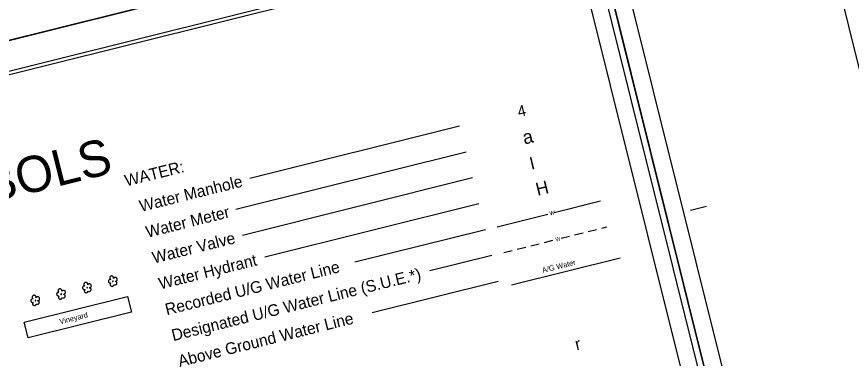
# Model space of a CAD drawing. Extents: x 1030323 to 1034123, y 654802 to 657751.
# Drawn here: x 1031795 to 1032422, y 655929 to 656186 of the extents above; entities that cross this region are included whole.
import ezdxf

# ---------------------------------------------------------------- set-up
doc = ezdxf.new("R2010")
doc.units = 0
for name, color, linetype in [('Sheet Cutting Line CELL', 7, 'Continuous'), ('Sheet Plot Border Inside CELL', 7, 'Continuous'), ('Sheet Plot Border Outside CELL', 7, 'Continuous'), ('Sheet Summary CELL', 7, 'Continuous'), ('Sheet Symbology CELL', 7, 'Continuous')]:
    doc.layers.add(name, color=color, linetype=linetype)

msp = doc.modelspace()

# ---------------------------------------------------------------- linework, layer by layer
at = {"layer": 'Sheet Cutting Line CELL'}
for p, q in [((1030589.1, 655869.05), (1032223.08, 656276.44)), ((1032223.08, 656276.44), (1030589.1, 655869.05)), ((1032223.08, 656276.44), (1032489.19, 655209.12))]:
    msp.add_line(p, q, dxfattribs=at)
at = {"layer": 'Sheet Plot Border Inside CELL'}
for points in [[(1033858.12, 656660.97), (1032241.12, 656257.81), (1032496.37, 655234.05), (1034113.37, 655637.21)], [(1030862.39, 654826.65), (1032479.39, 655229.81), (1032224.14, 656253.57), (1030607.14, 655850.41)]]:
    msp.add_lwpolyline(points, close=True, dxfattribs=at)
at = {"layer": 'Sheet Plot Border Outside CELL'}
for points in [[(1031956.96, 657343.76), (1030322.99, 656936.36), (1030589.1, 655869.05), (1032223.08, 656276.44)], [(1033857.05, 656683.84), (1032223.08, 656276.44), (1032489.19, 655209.12), (1034123.17, 655616.52)], [(1030855.21, 654801.72), (1032489.19, 655209.12), (1032223.08, 656276.44), (1030589.1, 655869.05)]]:
    msp.add_lwpolyline(points, close=True, dxfattribs=at)
at = {"layer": 'Sheet Summary CELL'}
msp.add_line((1032300.9, 656040.77), (1032313.03, 656043.8), dxfattribs=at)
msp.add_lwpolyline([(1033846.61, 656655.47), (1032391.16, 656292.59), (1032645.18, 655273.78), (1034100.62, 655636.66)], close=True, dxfattribs=at)
at = {"layer": 'Sheet Symbology CELL'}
for p, q in [((1032127.56, 656103.71), (1031970, 656064.42)), ((1032132.4, 656084.3), (1031959.65, 656041.23)), ((1032137.24, 656064.9), (1031964.49, 656021.82)), ((1032142.08, 656045.49), (1031981.22, 656005.38)), ((1032198.65, 656038.98), (1032233.29, 656047.62)), ((1032155.66, 656028.26), (1032193.8, 656037.77)), ((1032146.92, 656026.08), (1032048.81, 656001.62)), ((1032224.12, 656024.72), (1032230.42, 656026.29)), ((1032234.31, 656027.26), (1032238.13, 656028.21)), ((1032191.22, 656016.52), (1032197.53, 656018.09)), ((1032203.74, 656019.64), (1032210.05, 656021.21)), ((1032213.93, 656022.18), (1032220.24, 656023.75)), ((1032170.85, 656011.44), (1032177.15, 656013.01)), ((1032181.04, 656013.98), (1032187.34, 656015.55)), ((1032151.76, 656006.68), (1032105.17, 655995.06)), ((1032160.66, 656008.9), (1032166.97, 656010.47)), ((1032166.55, 655984.6), (1032248.07, 656004.93)), ((1032156.6, 655987.27), (1032061.79, 655963.63))]:
    msp.add_line(p, q, dxfattribs=at)
msp.add_lwpolyline([(1032212.63, 656248.07), (1030757.19, 655885.19), (1031010.96, 654867.37), (1032466.4, 655230.25)], close=True, dxfattribs=at)
for points in [[(1031848.31, 655984.64), (1031848.38, 655984.97), (1031848.36, 655985.28), (1031848.23, 655985.55), (1031848.11, 655985.83), (1031847.91, 655986.04), (1031847.7, 655986.25), (1031847.41, 655986.38), (1031847.13, 655986.46), (1031846.77, 655986.48), (1031846.53, 655986.42), (1031846.25, 655986.3), (1031845.98, 655986.13), (1031845.77, 655985.92), (1031845.58, 655985.66), (1031845.51, 655985.34), (1031845.47, 655985.07), (1031845.49, 655984.77), (1031845.57, 655984.48), (1031845.69, 655984.2), (1031845.89, 655983.99), (1031846.16, 655983.75), (1031845.88, 655983.83), (1031845.58, 655983.81), (1031845.29, 655983.74), (1031845.07, 655983.58), (1031844.85, 655983.42), (1031844.66, 655983.17), (1031844.51, 655982.92), (1031844.42, 655982.65), (1031844.44, 655982.39), (1031844.47, 655982.04), (1031844.58, 655981.81), (1031844.74, 655981.59), (1031844.99, 655981.4), (1031845.19, 655981.24), (1031845.47, 655981.15), (1031845.79, 655981.08), (1031846.05, 655981.09), (1031846.34, 655981.17), (1031846.12, 655981.01), (1031845.93, 655980.75), (1031845.83, 655980.52), (1031845.81, 655980.21), (1031845.78, 655979.89), (1031845.84, 655979.65), (1031845.96, 655979.37), (1031846.17, 655979.16), (1031846.38, 655978.96), (1031846.62, 655978.81), (1031846.9, 655978.73), (1031847.16, 655978.69), (1031847.45, 655978.76), (1031847.75, 655978.84), (1031847.98, 655978.95), (1031848.17, 655979.2), (1031848.38, 655979.41), (1031848.51, 655979.9)], [(1031867.71, 655989.48), (1031867.79, 655989.81), (1031867.76, 655990.11), (1031867.64, 655990.39), (1031867.52, 655990.67), (1031867.31, 655990.88), (1031867.11, 655991.08), (1031866.82, 655991.22), (1031866.54, 655991.3), (1031866.17, 655991.32), (1031865.93, 655991.25), (1031865.65, 655991.13), (1031865.39, 655990.96), (1031865.18, 655990.76), (1031864.98, 655990.5), (1031864.91, 655990.18), (1031864.88, 655989.91), (1031864.9, 655989.61), (1031864.97, 655989.31), (1031865.09, 655989.04), (1031865.3, 655988.83), (1031865.57, 655988.59), (1031865.29, 655988.67), (1031864.98, 655988.65), (1031864.69, 655988.58), (1031864.47, 655988.42), (1031864.26, 655988.26), (1031864.06, 655988.01), (1031863.92, 655987.76), (1031863.83, 655987.48), (1031863.84, 655987.23), (1031863.88, 655986.88), (1031863.99, 655986.65), (1031864.15, 655986.43), (1031864.4, 655986.24), (1031864.59, 655986.08), (1031864.87, 655985.99), (1031865.2, 655985.92), (1031865.45, 655985.93), (1031865.75, 655986), (1031865.53, 655985.85), (1031865.33, 655985.59), (1031865.24, 655985.36), (1031865.21, 655985.05), (1031865.19, 655984.73), (1031865.25, 655984.49), (1031865.37, 655984.21), (1031865.57, 655984), (1031865.78, 655983.8), (1031866.02, 655983.65), (1031866.3, 655983.57), (1031866.57, 655983.53), (1031866.86, 655983.6), (1031867.15, 655983.67), (1031867.38, 655983.78), (1031867.58, 655984.04), (1031867.78, 655984.24), (1031867.92, 655984.74)], [(1031867.31, 655987.58), (1031867.17, 655987.54), (1031867.08, 655987.47), (1031867, 655987.4), (1031867.03, 655987.25), (1031867.06, 655987.16), (1031867.18, 655987.08), (1031867.32, 655987.12), (1031867.42, 655987.14), (1031867.49, 655987.26), (1031867.51, 655987.42), (1031867.43, 655987.51), (1031867.31, 655987.58)], [(1031867.92, 655984.74), (1031868.58, 655984.55), (1031868.9, 655984.52), (1031869.2, 655984.55), (1031869.48, 655984.67), (1031869.7, 655984.83), (1031869.9, 655985.03), (1031870.1, 655985.29), (1031870.18, 655985.56), (1031870.22, 655985.83), (1031870.25, 655986.15), (1031870.12, 655986.43), (1031870, 655986.7), (1031869.74, 655986.95), (1031869.54, 655987.1), (1031869.26, 655987.19), (1031868.94, 655987.26), (1031869.24, 655987.29), (1031869.58, 655987.37), (1031869.8, 655987.53), (1031870.05, 655987.75), (1031870.26, 655987.95), (1031870.39, 655988.24), (1031870.46, 655988.57), (1031870.44, 655988.87), (1031870.42, 655989.18), (1031870.3, 655989.46), (1031870.13, 655989.72), (1031869.87, 655989.92), (1031869.57, 655990.1), (1031869.29, 655990.19), (1031868.97, 655990.21), (1031868.67, 655990.19), (1031868.38, 655990.11), (1031868.11, 655989.94), (1031867.91, 655989.74), (1031867.71, 655989.48)], [(1031828.9, 655979.81), (1031828.97, 655980.13), (1031828.95, 655980.44), (1031828.83, 655980.72), (1031828.71, 655980.99), (1031828.5, 655981.2), (1031828.3, 655981.41), (1031828, 655981.54), (1031827.73, 655981.63), (1031827.36, 655981.64), (1031827.12, 655981.58), (1031826.84, 655981.46), (1031826.57, 655981.29), (1031826.37, 655981.08), (1031826.17, 655980.83), (1031826.1, 655980.5), (1031826.06, 655980.23), (1031826.09, 655979.93), (1031826.16, 655979.64), (1031826.28, 655979.36), (1031826.49, 655979.15), (1031826.75, 655978.91), (1031826.48, 655979), (1031826.17, 655978.97), (1031825.88, 655978.9), (1031825.66, 655978.74), (1031825.44, 655978.58), (1031825.25, 655978.33), (1031825.1, 655978.09), (1031825.02, 655977.81), (1031825.03, 655977.55), (1031825.07, 655977.2), (1031825.18, 655976.97), (1031825.33, 655976.75), (1031825.59, 655976.56), (1031825.78, 655976.4), (1031826.06, 655976.32), (1031826.39, 655976.24), (1031826.64, 655976.25), (1031826.93, 655976.33), (1031826.72, 655976.17), (1031826.52, 655975.91), (1031826.42, 655975.68), (1031826.4, 655975.37), (1031826.38, 655975.05), (1031826.44, 655974.81), (1031826.56, 655974.53), (1031826.76, 655974.33), (1031826.97, 655974.12), (1031827.21, 655973.97), (1031827.49, 655973.89), (1031827.76, 655973.85), (1031828.05, 655973.93), (1031828.34, 655974), (1031828.57, 655974.11), (1031828.76, 655974.36), (1031828.97, 655974.57), (1031829.1, 655975.06)], [(1031829.1, 655975.06), (1031829.77, 655974.87), (1031830.09, 655974.85), (1031830.39, 655974.87), (1031830.67, 655974.99), (1031830.89, 655975.15), (1031831.09, 655975.35), (1031831.29, 655975.61), (1031831.37, 655975.89), (1031831.41, 655976.15), (1031831.43, 655976.47), (1031831.31, 655976.75), (1031831.19, 655977.03), (1031830.92, 655977.27), (1031830.73, 655977.43), (1031830.45, 655977.51), (1031830.12, 655977.59), (1031830.43, 655977.61), (1031830.77, 655977.69), (1031830.99, 655977.85), (1031831.24, 655978.07), (1031831.45, 655978.28), (1031831.58, 655978.57), (1031831.65, 655978.89), (1031831.63, 655979.2), (1031831.6, 655979.5), (1031831.48, 655979.78), (1031831.31, 655980.05), (1031831.06, 655980.24), (1031830.76, 655980.42), (1031830.48, 655980.51), (1031830.16, 655980.53), (1031829.86, 655980.51), (1031829.57, 655980.44), (1031829.3, 655980.27), (1031829.1, 655980.06), (1031828.9, 655979.81)], [(1031847.91, 655982.74), (1031847.76, 655982.7), (1031847.67, 655982.63), (1031847.59, 655982.56), (1031847.63, 655982.41), (1031847.65, 655982.32), (1031847.77, 655982.24), (1031847.92, 655982.28), (1031848.01, 655982.3), (1031848.09, 655982.43), (1031848.1, 655982.58), (1031848.03, 655982.67), (1031847.91, 655982.74)], [(1031848.51, 655979.9), (1031849.18, 655979.71), (1031849.49, 655979.68), (1031849.8, 655979.71), (1031850.07, 655979.83), (1031850.29, 655979.99), (1031850.5, 655980.19), (1031850.69, 655980.45), (1031850.78, 655980.73), (1031850.81, 655980.99), (1031850.84, 655981.31), (1031850.72, 655981.59), (1031850.6, 655981.87), (1031850.33, 655982.11), (1031850.14, 655982.27), (1031849.86, 655982.35), (1031849.53, 655982.42), (1031849.83, 655982.45), (1031850.17, 655982.53), (1031850.39, 655982.69), (1031850.65, 655982.91), (1031850.85, 655983.11), (1031850.99, 655983.41), (1031851.06, 655983.73), (1031851.03, 655984.04), (1031851.01, 655984.34), (1031850.89, 655984.62), (1031850.72, 655984.89), (1031850.47, 655985.08), (1031850.16, 655985.26), (1031849.88, 655985.35), (1031849.57, 655985.37), (1031849.27, 655985.35), (1031848.97, 655985.27), (1031848.71, 655985.11), (1031848.5, 655984.9), (1031848.31, 655984.64)], [(1031800.64, 655956.53), (1031878.27, 655975.88), (1031881.17, 655964.24), (1031803.55, 655944.88), (1031800.64, 655956.53)], [(1031809.49, 655974.97), (1031809.57, 655975.3), (1031809.54, 655975.6), (1031809.42, 655975.88), (1031809.3, 655976.16), (1031809.1, 655976.36), (1031808.89, 655976.57), (1031808.6, 655976.7), (1031808.32, 655976.79), (1031807.96, 655976.8), (1031807.71, 655976.74), (1031807.43, 655976.62), (1031807.17, 655976.45), (1031806.96, 655976.24), (1031806.77, 655975.99), (1031806.69, 655975.66), (1031806.66, 655975.39), (1031806.68, 655975.09), (1031806.75, 655974.8), (1031806.88, 655974.52), (1031807.08, 655974.31), (1031807.35, 655974.07), (1031807.07, 655974.16), (1031806.77, 655974.13), (1031806.47, 655974.06), (1031806.26, 655973.9), (1031806.04, 655973.75), (1031805.84, 655973.49), (1031805.7, 655973.25), (1031805.61, 655972.97), (1031805.63, 655972.71), (1031805.66, 655972.36), (1031805.77, 655972.13), (1031805.93, 655971.91), (1031806.18, 655971.72), (1031806.38, 655971.56), (1031806.66, 655971.48), (1031806.98, 655971.4), (1031807.24, 655971.42), (1031807.53, 655971.49), (1031807.31, 655971.33), (1031807.12, 655971.08), (1031807.02, 655970.85), (1031806.99, 655970.53), (1031806.97, 655970.22), (1031807.03, 655969.97), (1031807.15, 655969.69), (1031807.36, 655969.49), (1031807.56, 655969.28), (1031807.81, 655969.14), (1031808.08, 655969.05), (1031808.35, 655969.01), (1031808.64, 655969.09), (1031808.93, 655969.16), (1031809.16, 655969.27), (1031809.36, 655969.52), (1031809.56, 655969.73), (1031809.7, 655970.23)], [(1031809.7, 655970.23), (1031810.36, 655970.03), (1031810.68, 655970.01), (1031810.98, 655970.03), (1031811.26, 655970.15), (1031811.48, 655970.31), (1031811.69, 655970.52), (1031811.88, 655970.77), (1031811.97, 655971.05), (1031812, 655971.32), (1031812.03, 655971.63), (1031811.91, 655971.91), (1031811.79, 655972.19), (1031811.52, 655972.43), (1031811.32, 655972.59), (1031811.05, 655972.67), (1031810.72, 655972.75), (1031811.02, 655972.77), (1031811.36, 655972.86), (1031811.58, 655973.01), (1031811.83, 655973.23), (1031812.04, 655973.44), (1031812.17, 655973.73), (1031812.25, 655974.06), (1031812.22, 655974.36), (1031812.2, 655974.66), (1031812.08, 655974.94), (1031811.91, 655975.21), (1031811.65, 655975.4), (1031811.35, 655975.58), (1031811.07, 655975.67), (1031810.76, 655975.69), (1031810.45, 655975.67), (1031810.16, 655975.6), (1031809.9, 655975.43), (1031809.69, 655975.22), (1031809.49, 655974.97)], [(1031828.5, 655977.9), (1031828.35, 655977.87), (1031828.27, 655977.79), (1031828.18, 655977.72), (1031828.22, 655977.58), (1031828.24, 655977.48), (1031828.37, 655977.41), (1031828.51, 655977.44), (1031828.61, 655977.47), (1031828.68, 655977.59), (1031828.69, 655977.74), (1031828.62, 655977.83), (1031828.5, 655977.9)], [(1031809.09, 655973.06), (1031808.95, 655973.03), (1031808.86, 655972.96), (1031808.78, 655972.88), (1031808.81, 655972.74), (1031808.84, 655972.64), (1031808.96, 655972.57), (1031809.11, 655972.6), (1031809.2, 655972.63), (1031809.28, 655972.75), (1031809.29, 655972.91), (1031809.21, 655972.99), (1031809.09, 655973.06)]]:
    msp.add_lwpolyline(points, dxfattribs=at)

# ---------------------------------------------------------------- texts
for s, height, rotation, p in [('4', 8.25, 14, (1032172.12, 656110.56)), ('CONVENTIONAL  PLAN SHEET SYMBOLS', 27.2003, 14, (1031170.08, 655894.92)), ('a', 10.2, 14.00002, (1032176.25, 656089.98)), ('I', 9.37, 14, (1032181.38, 656071.07)), ('WATER:', 8.75, 14, (1031877.32, 656058.49)), ('Water Manhole', 8.75, 14, (1031888.32, 656039.38)), ('H', 9.75, 14, (1032186.09, 656051.44)), ('Water Meter', 8.75, 14, (1031893.16, 656019.97)), ('W', 3, 14, (1032195.52, 656036.66)), ('Water Valve', 8.75, 14, (1031898, 656000.57)), ('W', 3, 14, (1032199.93, 656017.14)), ('Water Hydrant', 8.75, 14, (1031902.84, 655981.16)), ('Recorded U/G Water Line', 8.75, 14, (1031907.67, 655961.76)), ('A/G Water', 4, 14, (1032190.01, 655993.54)), ('Designated U/G Water Line (S.U.E.*)', 8.75, 14, (1031912.51, 655942.35)), ('Vineyard', 4, 14.00002, (1031827.64, 655955.01)), ('Above Ground Water Line', 8.75, 14, (1031917.35, 655922.95)), ('r', 9, 14, (1032215.39, 655935.46))]:
    msp.add_text(s, height=height, rotation=rotation, dxfattribs=at).set_placement(p)

doc.saveas('drawing.dxf')
